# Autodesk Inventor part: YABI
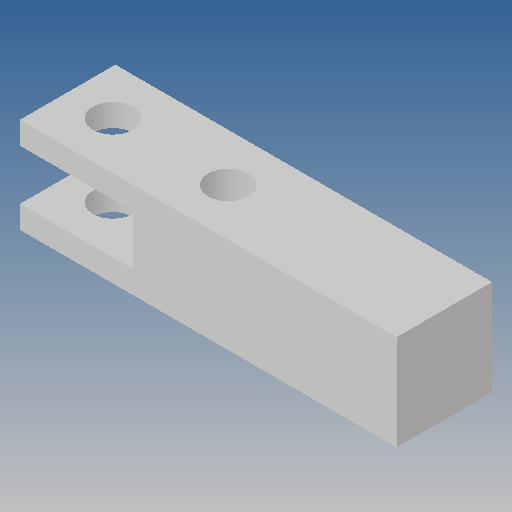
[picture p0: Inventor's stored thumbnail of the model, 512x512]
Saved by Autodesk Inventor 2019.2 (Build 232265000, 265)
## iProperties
Created: 2013-07
Part Number: YABI
Material: Ogólny
Document SubType Name: Modeling
Designer: CADENGINEERING4
Density: 1 g/cm^3
Appearance: Domyślna
Author: CADENGINEERING4
Revision Number: ÈÎºÎ
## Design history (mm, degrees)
feature "CALC50YB-1-solid1"
node "Bryła1"
